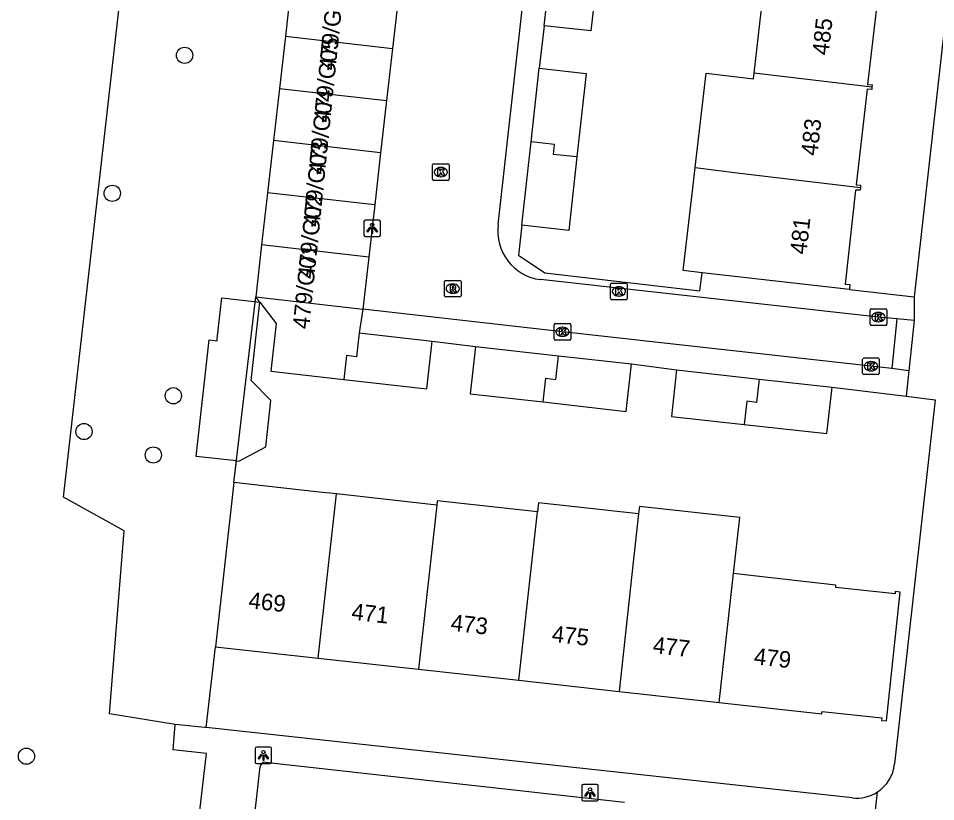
# Model space of a CAD drawing. Extents: x 161928 to 163055, y 386475 to 387428.
# Drawn here: x 162043.6 to 162098.9, y 387056.3 to 387103.5 of the extents above; entities that cross this region are included whole.
import ezdxf

# ---------------------------------------------------------------- set-up
doc = ezdxf.new("R2010")
doc.units = 0
for name, color, linetype in [('IMGEO_Boom', 7, 'Continuous'), ('IMGEO_Groenvoorziening', 7, 'Continuous'), ('IMGEO_Hek', 7, 'Continuous'), ('IMGEO_Kolk', 7, 'Continuous'), ('IMGEO_Lichtpunt', 7, 'Continuous'), ('IMGEO_Pand', 7, 'Continuous'), ('IMGEO_Pand_nummerreeks', 7, 'Continuous'), ('IMGEO_Rijbaan_lokaal_open', 7, 'Continuous'), ('IMGEO_Rioolput', 7, 'Continuous'), ('IMGEO_Voetpad_open', 7, 'Continuous')]:
    doc.layers.add(name, color=color, linetype=linetype)

msp = doc.modelspace()

# ---------------------------------------------------------------- linework, layer by layer
at = {"layer": 'IMGEO_Boom'}
for centre in [(162053.658, 387101.262), (162049.298, 387092.95), (162052.981, 387080.756), (162047.592, 387078.601), (162051.773, 387077.187), (162044.124, 387059.042)]:
    msp.add_circle(centre, 0.489, dxfattribs=at)
at = {"layer": 'IMGEO_Groenvoorziening'}
for points in [[(162053.084, 387060.96), (162049.139, 387061.592), (162050.014, 387072.611), (162046.359, 387074.644), (162054.161, 387143.235), (162059.064, 387145.048), (162059.632, 387154.151), (162065.287, 387153.527)], [(162056.626, 387075.526), (162056.78, 387076.828)], [(162054.959, 387060.765), (162055.525, 387065.64)]]:
    msp.add_lwpolyline(points, dxfattribs=at)
at = {"layer": 'IMGEO_Hek'}
msp.add_lwpolyline([(162056.626, 387075.526), (162057.948, 387086.72)], dxfattribs=at)
at = {"layer": 'IMGEO_Kolk'}
for p, q in [((162068.606, 387093.806), (162068.606, 387094.658)), ((162068.681, 387094.732), (162069.533, 387094.732)), ((162069.094, 387094.512), (162069.119, 387094.512)), ((162069.607, 387094.658), (162069.607, 387093.806)), ((162069.117, 387093.952), (162069.092, 387093.952)), ((162069.533, 387093.732), (162068.681, 387093.732)), ((162079.341, 387086.618), (162079.341, 387087.47)), ((162079.416, 387087.544), (162080.268, 387087.544)), ((162079.829, 387087.324), (162079.854, 387087.324)), ((162080.342, 387087.47), (162080.342, 387086.618)), ((162079.852, 387086.764), (162079.827, 387086.764)), ((162080.268, 387086.544), (162079.416, 387086.544)), ((162094.987, 387085.068), (162094.987, 387085.92)), ((162095.062, 387085.994), (162095.914, 387085.994)), ((162095.475, 387085.774), (162095.5, 387085.774)), ((162095.988, 387085.92), (162095.988, 387085.068)), ((162075.943, 387084.181), (162075.943, 387085.033)), ((162076.018, 387085.107), (162076.87, 387085.107)), ((162076.944, 387085.033), (162076.944, 387084.181)), ((162095.498, 387085.214), (162095.473, 387085.214)), ((162076.431, 387084.887), (162076.456, 387084.887)), ((162095.914, 387084.994), (162095.062, 387084.994)), ((162076.87, 387084.107), (162076.018, 387084.107)), ((162076.454, 387084.327), (162076.429, 387084.327)), ((162094.539, 387082.106), (162094.539, 387082.958)), ((162094.614, 387083.032), (162095.466, 387083.032)), ((162095.027, 387082.812), (162095.052, 387082.812)), ((162095.54, 387082.958), (162095.54, 387082.106)), ((162095.05, 387082.252), (162095.025, 387082.252)), ((162095.466, 387082.032), (162094.614, 387082.032))]:
    msp.add_line(p, q, dxfattribs=at)
for points in [[(162068.606, 387093.806), (162068.606, 387094.658)], [(162068.681, 387094.732), (162069.533, 387094.732)], [(162068.927, 387094.432), (162069.05, 387094.432), (162069.05, 387094.281), (162069.18, 387094.432), (162069.344, 387094.432), (162069.198, 387094.281), (162069.351, 387094.032), (162069.199, 387094.032), (162069.114, 387094.196), (162069.05, 387094.129), (162069.05, 387094.032), (162068.927, 387094.032), (162068.927, 387094.432)], [(162069.607, 387094.658), (162069.607, 387093.806)], [(162069.533, 387093.732), (162068.681, 387093.732)], [(162079.341, 387086.618), (162079.341, 387087.47)], [(162079.416, 387087.544), (162080.268, 387087.544)], [(162079.662, 387087.244), (162079.785, 387087.244), (162079.785, 387087.093), (162079.915, 387087.244), (162080.079, 387087.244), (162079.933, 387087.093), (162080.086, 387086.844), (162079.934, 387086.844), (162079.849, 387087.008), (162079.785, 387086.941), (162079.785, 387086.844), (162079.662, 387086.844), (162079.662, 387087.244)], [(162080.342, 387087.47), (162080.342, 387086.618)], [(162080.268, 387086.544), (162079.416, 387086.544)], [(162094.987, 387085.068), (162094.987, 387085.92)], [(162095.062, 387085.994), (162095.914, 387085.994)], [(162095.308, 387085.694), (162095.431, 387085.694), (162095.431, 387085.543), (162095.561, 387085.694), (162095.725, 387085.694), (162095.579, 387085.543), (162095.732, 387085.294), (162095.58, 387085.294), (162095.495, 387085.458), (162095.431, 387085.391), (162095.431, 387085.294), (162095.308, 387085.294), (162095.308, 387085.694)], [(162095.988, 387085.92), (162095.988, 387085.068)], [(162075.943, 387084.181), (162075.943, 387085.033)], [(162076.018, 387085.107), (162076.87, 387085.107)], [(162076.944, 387085.033), (162076.944, 387084.181)], [(162076.264, 387084.807), (162076.387, 387084.807), (162076.387, 387084.656), (162076.517, 387084.807), (162076.681, 387084.807), (162076.535, 387084.656), (162076.688, 387084.407), (162076.536, 387084.407), (162076.451, 387084.571), (162076.387, 387084.504), (162076.387, 387084.407), (162076.264, 387084.407), (162076.264, 387084.807)], [(162095.914, 387084.994), (162095.062, 387084.994)], [(162076.87, 387084.107), (162076.018, 387084.107)], [(162094.539, 387082.106), (162094.539, 387082.958)], [(162094.614, 387083.032), (162095.466, 387083.032)], [(162095.54, 387082.958), (162095.54, 387082.106)], [(162094.86, 387082.732), (162094.983, 387082.732), (162094.983, 387082.581), (162095.113, 387082.732), (162095.277, 387082.732), (162095.131, 387082.581), (162095.284, 387082.332), (162095.132, 387082.332), (162095.047, 387082.496), (162094.983, 387082.429), (162094.983, 387082.332), (162094.86, 387082.332), (162094.86, 387082.732)], [(162095.466, 387082.032), (162094.614, 387082.032)]]:
    msp.add_lwpolyline(points, dxfattribs=at)
for centre, start, end in [((162068.683, 387094.656), 91.552, 178.448), ((162068.683, 387094.656), 91.552, 178.448), ((162069.531, 387094.656), 1.552, 88.448), ((162069.531, 387094.656), 1.552, 88.448), ((162068.683, 387093.808), 181.552, 268.448), ((162068.683, 387093.808), 181.552, 268.448), ((162069.531, 387093.808), 271.552, 358.448), ((162069.531, 387093.808), 271.552, 358.448), ((162079.418, 387087.468), 91.552, 178.448), ((162079.418, 387087.468), 91.552, 178.448), ((162080.266, 387087.468), 1.552, 88.448), ((162080.266, 387087.468), 1.552, 88.448), ((162079.418, 387086.62), 181.552, 268.448), ((162079.418, 387086.62), 181.552, 268.448), ((162080.266, 387086.62), 271.552, 358.448), ((162080.266, 387086.62), 271.552, 358.448), ((162095.064, 387085.918), 91.552, 178.448), ((162095.064, 387085.918), 91.552, 178.448), ((162095.912, 387085.918), 1.552, 88.448), ((162095.912, 387085.918), 1.552, 88.448), ((162076.02, 387085.031), 91.552, 178.448), ((162076.02, 387085.031), 91.552, 178.448), ((162076.868, 387085.031), 1.552, 88.448), ((162076.868, 387085.031), 1.552, 88.448), ((162095.064, 387085.07), 181.552, 268.448), ((162095.064, 387085.07), 181.552, 268.448), ((162095.912, 387085.07), 271.552, 358.448), ((162095.912, 387085.07), 271.552, 358.448), ((162076.02, 387084.183), 181.552, 268.448), ((162076.02, 387084.183), 181.552, 268.448), ((162076.868, 387084.183), 271.552, 358.448), ((162076.868, 387084.183), 271.552, 358.448), ((162094.616, 387082.956), 91.552, 178.448), ((162094.616, 387082.956), 91.552, 178.448), ((162095.464, 387082.956), 1.552, 88.448), ((162095.464, 387082.956), 1.552, 88.448), ((162094.616, 387082.108), 181.552, 268.448), ((162094.616, 387082.108), 181.552, 268.448), ((162095.464, 387082.108), 271.552, 358.448), ((162095.464, 387082.108), 271.552, 358.448)]:
    msp.add_arc(centre, 0.0765, start, end, dxfattribs=at)
for centre, major_axis, ratio, start_param, end_param in [((162069.093, 387094.232), (-0.387, 0.002), 0.722429, 4.712389, 7.853982), ((162069.118, 387094.232), (-0.39, 0.002), 0.717154, 1.570796, 4.712389), ((162079.828, 387087.044), (-0.387, 0.002), 0.722429, 4.712389, 7.853982), ((162079.853, 387087.044), (-0.39, 0.002), 0.717154, 1.570796, 4.712389), ((162095.474, 387085.494), (-0.387, 0.002), 0.722429, 4.712389, 7.853982), ((162095.499, 387085.494), (-0.39, 0.002), 0.717154, 1.570796, 4.712389), ((162076.43, 387084.607), (-0.387, 0.002), 0.722429, 4.712389, 7.853982), ((162076.455, 387084.607), (-0.39, 0.002), 0.717154, 1.570796, 4.712389), ((162095.026, 387082.532), (-0.387, 0.002), 0.722429, 4.712389, 7.853982), ((162095.051, 387082.532), (-0.39, 0.002), 0.717154, 1.570796, 4.712389)]:
    msp.add_ellipse(centre, major_axis=major_axis, ratio=ratio, start_param=start_param, end_param=end_param, dxfattribs=at)
at = {"layer": 'IMGEO_Lichtpunt'}
for p, q in [((162064.468, 387091.246), (162064.468, 387090.439)), ((162064.468, 387091.246), (162064.468, 387090.439)), ((162065.37, 387091.341), (162064.562, 387091.341)), ((162065.37, 387091.341), (162064.562, 387091.341)), ((162065.464, 387090.439), (162065.464, 387091.246)), ((162065.464, 387090.439), (162065.464, 387091.246)), ((162064.562, 387090.345), (162065.37, 387090.345)), ((162064.562, 387090.345), (162065.37, 387090.345)), ((162058.813, 387059.59), (162058.005, 387059.59)), ((162058.813, 387059.59), (162058.005, 387059.59)), ((162057.911, 387059.495), (162057.911, 387058.688)), ((162057.911, 387059.495), (162057.911, 387058.688)), ((162058.907, 387058.688), (162058.907, 387059.495)), ((162058.907, 387058.688), (162058.907, 387059.495)), ((162058.005, 387058.594), (162058.813, 387058.594)), ((162058.005, 387058.594), (162058.813, 387058.594)), ((162077.605, 387057.248), (162077.605, 387056.441)), ((162077.605, 387057.248), (162077.605, 387056.441)), ((162078.507, 387057.343), (162077.699, 387057.343)), ((162078.507, 387057.343), (162077.699, 387057.343)), ((162078.601, 387056.441), (162078.601, 387057.248)), ((162078.601, 387056.441), (162078.601, 387057.248)), ((162077.699, 387056.347), (162078.507, 387056.347)), ((162077.699, 387056.347), (162078.507, 387056.347))]:
    msp.add_line(p, q, dxfattribs=at)
for points in [[(162064.842, 387090.91), (162064.881, 387090.882), (162064.693, 387090.62), (162064.655, 387090.647), (162064.842, 387090.91)], [(162064.944, 387090.862), (162064.991, 387090.862), (162064.991, 387090.54), (162064.944, 387090.54), (162064.944, 387090.862)], [(162065.054, 387090.882), (162065.092, 387090.909), (162065.279, 387090.647), (162065.24, 387090.619), (162065.054, 387090.882)], [(162058.285, 387059.159), (162058.324, 387059.131), (162058.136, 387058.869), (162058.098, 387058.896), (162058.285, 387059.159)], [(162058.387, 387059.111), (162058.434, 387059.111), (162058.434, 387058.789), (162058.387, 387058.789), (162058.387, 387059.111)], [(162058.497, 387059.131), (162058.535, 387059.158), (162058.722, 387058.896), (162058.683, 387058.868), (162058.497, 387059.131)], [(162077.979, 387056.912), (162078.018, 387056.884), (162077.83, 387056.622), (162077.792, 387056.649), (162077.979, 387056.912)], [(162078.081, 387056.864), (162078.128, 387056.864), (162078.128, 387056.542), (162078.081, 387056.542), (162078.081, 387056.864)], [(162078.191, 387056.884), (162078.229, 387056.911), (162078.416, 387056.649), (162078.377, 387056.621), (162078.191, 387056.884)]]:
    msp.add_lwpolyline(points, dxfattribs=at)
for centre in [(162064.967, 387091.044), (162058.41, 387059.293), (162078.104, 387057.046)]:
    msp.add_circle(centre, 0.0994, dxfattribs=at)
for centre, start, end in [((162064.562, 387091.246), 90, 180), ((162064.562, 387091.246), 90, 180), ((162065.37, 387091.246), 0, 90), ((162065.37, 387091.246), 0, 90), ((162064.562, 387090.439), 180, 270), ((162064.562, 387090.439), 180, 270), ((162065.37, 387090.439), 270, 0), ((162065.37, 387090.439), 270, 360), ((162058.005, 387059.495), 90, 180), ((162058.005, 387059.495), 90, 180), ((162058.813, 387059.495), 0, 90), ((162058.813, 387059.495), 0, 90), ((162058.005, 387058.688), 180, 270), ((162058.005, 387058.688), 180, 270), ((162058.813, 387058.688), 270, 0), ((162058.813, 387058.688), 270, 360), ((162077.699, 387057.248), 90, 180), ((162077.699, 387057.248), 90, 180), ((162078.507, 387057.248), 0, 90), ((162078.507, 387057.248), 0, 90), ((162077.699, 387056.441), 180, 270), ((162077.699, 387056.441), 180, 270), ((162078.507, 387056.441), 270, 0), ((162078.507, 387056.441), 270, 360)]:
    msp.add_arc(centre, 0.0946, start, end, dxfattribs=at)
at = {"layer": 'IMGEO_Pand'}
for points in [[(162075.339, 387103.045), (162075.897, 387108.04)], [(162078.646, 387107.128), (162078.155, 387102.731), (162075.339, 387103.045)], [(162087.989, 387100.194), (162088.688, 387106.183)], [(162060.089, 387105.551), (162059.732, 387102.411)], [(162095.733, 387105.345), (162095.715, 387105.165), (162095.484, 387105.185), (162094.822, 387099.501), (162095.106, 387099.49), (162095.099, 387099.348)], [(162066.553, 387104.814), (162066.195, 387101.674)], [(162059.732, 387102.411), (162059.375, 387099.271)], [(162059.732, 387102.411), (162066.195, 387101.674)], [(162066.195, 387101.674), (162065.837, 387098.534)], [(162074.55, 387096.053), (162075.044, 387100.482)], [(162075.044, 387100.482), (162077.87, 387100.167), (162077.309, 387095.141)], [(162084.441, 387094.508), (162085.103, 387100.194), (162087.95, 387099.857), (162087.989, 387100.194)], [(162095.099, 387099.348), (162087.989, 387100.194)], [(162059.375, 387099.271), (162059.018, 387096.13)], [(162059.375, 387099.271), (162065.837, 387098.534)], [(162095.099, 387099.348), (162095.091, 387099.204), (162094.808, 387099.215), (162094.154, 387093.459), (162094.408, 387093.45), (162094.402, 387093.292)], [(162065.837, 387098.534), (162065.479, 387095.394)], [(162059.018, 387096.13), (162058.661, 387092.99)], [(162065.479, 387095.394), (162059.018, 387096.13)], [(162073.989, 387091.03), (162074.55, 387096.053)], [(162077.309, 387095.141), (162075.896, 387095.298), (162075.963, 387095.896), (162074.55, 387096.053)], [(162065.479, 387095.394), (162065.122, 387092.254)], [(162077.309, 387095.141), (162076.815, 387090.715), (162073.989, 387091.03)], [(162084.854, 387088.159), (162083.718, 387088.293), (162084.296, 387093.26), (162084.441, 387094.508)], [(162084.441, 387094.508), (162086.971, 387094.176), (162094.402, 387093.292)], [(162094.402, 387093.292), (162094.397, 387093.134), (162094.114, 387093.144), (162093.483, 387087.47), (162093.763, 387087.46), (162093.752, 387087.149)], [(162058.661, 387092.99), (162058.304, 387089.85)], [(162065.122, 387092.254), (162058.661, 387092.99)], [(162065.122, 387092.254), (162064.764, 387089.114)], [(162058.304, 387089.85), (162057.948, 387086.72)], [(162064.764, 387089.114), (162058.304, 387089.85)], [(162064.764, 387089.114), (162064.406, 387085.974)], [(162093.752, 387087.149), (162084.854, 387088.159)], [(162056.78, 387076.828), (162054.365, 387077.097), (162055.146, 387084.117), (162055.614, 387084.065), (162055.628, 387084.186), (162055.903, 387086.656), (162058.191, 387086.401)], [(162057.948, 387086.72), (162064.406, 387085.974)], [(162058.191, 387086.401), (162057.948, 387086.72)], [(162056.78, 387076.828), (162056.933, 387076.811), (162058.546, 387077.681), (162058.856, 387080.462), (162057.665, 387081.683), (162058.191, 387086.401)], [(162058.191, 387086.401), (162059.176, 387085.107), (162058.853, 387082.236), (162063.258, 387081.739)], [(162064.406, 387085.974), (162064.188, 387084.542)], [(162064.188, 387084.542), (162064.017, 387083.107), (162063.42, 387083.174), (162063.258, 387081.739)], [(162064.188, 387084.542), (162068.583, 387084.046)], [(162063.258, 387081.739), (162068.26, 387081.175), (162068.583, 387084.046)], [(162071.203, 387083.729), (162070.881, 387080.877), (162075.279, 387080.381)], [(162071.203, 387083.729), (162076.198, 387083.165)], [(162075.279, 387080.381), (162075.44, 387081.806), (162076.037, 387081.738), (162076.198, 387083.165)], [(162076.198, 387083.165), (162080.595, 387082.669)], [(162075.279, 387080.381), (162080.273, 387079.817), (162080.595, 387082.669)], [(162083.314, 387082.31), (162083.005, 387079.516), (162087.396, 387079.03)], [(162083.314, 387082.31), (162088.303, 387081.757)], [(162088.303, 387081.757), (162088.148, 387080.359), (162087.551, 387080.425), (162087.396, 387079.03)], [(162088.303, 387081.757), (162092.693, 387081.271)], [(162087.396, 387079.03), (162092.384, 387078.477), (162092.693, 387081.271)], [(162056.626, 387075.526), (162055.525, 387065.64)], [(162062.813, 387074.84), (162061.596, 387074.975), (162056.626, 387075.526)], [(162061.718, 387064.954), (162062.813, 387074.84)], [(162068.857, 387074.171), (162062.813, 387074.84)], [(162068.857, 387074.171), (162067.762, 387064.284)], [(162074.93, 387073.76), (162068.886, 387074.43), (162068.857, 387074.171)], [(162081.034, 387073.639), (162074.99, 387074.308), (162074.93, 387073.76)], [(162086.755, 387070.048), (162087.129, 387073.423), (162081.084, 387074.093), (162081.034, 387073.639)], [(162073.806, 387063.615), (162074.67, 387071.416), (162074.93, 387073.76)], [(162081.034, 387073.639), (162080.712, 387070.732), (162079.85, 387062.945)], [(162085.894, 387062.276), (162086.755, 387070.048)], [(162085.894, 387062.276), (162092.086, 387061.59), (162092.103, 387061.743), (162095.695, 387061.347), (162095.679, 387061.197), (162095.977, 387061.165), (162096.805, 387068.934), (162096.507, 387068.965), (162096.491, 387068.817), (162092.914, 387069.214), (162092.929, 387069.349), (162087.961, 387069.911), (162086.755, 387070.048)], [(162055.525, 387065.64), (162061.718, 387064.954)], [(162061.718, 387064.954), (162067.762, 387064.284)], [(162067.762, 387064.284), (162073.806, 387063.615)], [(162073.806, 387063.615), (162079.85, 387062.945)], [(162079.85, 387062.945), (162085.894, 387062.276)]]:
    msp.add_lwpolyline(points, dxfattribs=at)
at = {"layer": 'IMGEO_Rijbaan_lokaal_open'}
for points in [[(162072.569, 387091.066), (162076.462, 387125.985), (162069.057, 387126.795)], [(162096.605, 387085.381), (162095.488, 387085.494), (162075.107, 387087.756)], [(162096.298, 387082.392), (162095.04, 387082.532), (162076.444, 387084.607), (162064.406, 387085.974)], [(162096.605, 387085.381), (162096.298, 387082.392)], [(162097.645, 387085.295), (162096.605, 387085.381)], [(162097.645, 387085.295), (162097.329, 387082.251)], [(162097.329, 387082.251), (162096.298, 387082.392)]]:
    msp.add_lwpolyline(points, dxfattribs=at)
msp.add_arc((162075.456, 387090.652), 2.916, 171.8302, 263.1294, dxfattribs=at)
at = {"layer": 'IMGEO_Rioolput'}
for p, q in [((162069.323, 387086.782), (162069.323, 387087.634)), ((162069.398, 387087.708), (162070.25, 387087.708)), ((162069.811, 387087.488), (162069.836, 387087.488)), ((162070.324, 387087.634), (162070.324, 387086.782)), ((162070.25, 387086.708), (162069.398, 387086.708)), ((162069.834, 387086.928), (162069.809, 387086.928))]:
    msp.add_line(p, q, dxfattribs=at)
for points in [[(162069.323, 387086.782), (162069.323, 387087.634)], [(162069.398, 387087.708), (162070.25, 387087.708)], [(162069.912, 387087.406), (162069.66, 387087.408), (162069.66, 387087.008)], [(162069.838, 387087.327), (162069.784, 387087.327), (162069.784, 387087.246)], [(162069.784, 387087.246), (162069.836, 387087.246)], [(162070.324, 387087.634), (162070.324, 387086.782)], [(162070.25, 387086.708), (162069.398, 387086.708)], [(162069.66, 387087.008), (162069.784, 387087.008), (162069.784, 387087.17), (162069.795, 387087.17)], [(162069.842, 387087.141), (162069.913, 387087.008), (162070.053, 387087.008), (162069.988, 387087.134)]]:
    msp.add_lwpolyline(points, dxfattribs=at)
for centre, radius, start, end in [((162069.4, 387087.632), 0.0765, 91.552, 178.448), ((162069.4, 387087.632), 0.0765, 91.552, 178.448), ((162069.82, 387087.435), 0.19, 274.7715, 282.9687), ((162069.844, 387087.231), 0.0964, 77.0061, 93.1865), ((162069.858, 387087.288), 0.0378, 276.6634, 79.6772), ((162069.911, 387087.296), 0.109, 350.3612, 89.416), ((162069.909, 387087.296), 0.112, 277.5842, 350.9817), ((162070.248, 387087.632), 0.0765, 1.552, 88.448), ((162070.248, 387087.632), 0.0765, 1.552, 88.448), ((162069.4, 387086.784), 0.0765, 181.552, 268.448), ((162069.4, 387086.784), 0.0765, 181.552, 268.448), ((162069.794, 387087.117), 0.0533, 26.0293, 88.6989), ((162069.893, 387087.081), 0.108, 29.5134, 73.7905), ((162070.248, 387086.784), 0.0765, 271.552, 358.448), ((162070.248, 387086.784), 0.0765, 271.552, 358.448)]:
    msp.add_arc(centre, radius, start, end, dxfattribs=at)
for centre, major_axis, ratio, start_param, end_param in [((162069.81, 387087.208), (-0.387, 0.002), 0.722429, 4.712389, 7.853982), ((162069.835, 387087.208), (-0.39, 0.002), 0.717154, 1.570796, 4.712389)]:
    msp.add_ellipse(centre, major_axis=major_axis, ratio=ratio, start_param=start_param, end_param=end_param, dxfattribs=at)
at = {"layer": 'IMGEO_Voetpad_open'}
for points in [[(162101.718, 387123.058), (162097.649, 387086.723)], [(162075.339, 387103.045), (162075.044, 387100.482)], [(162073.989, 387091.03), (162073.787, 387089.221), (162075.378, 387088.153), (162084.728, 387087.083), (162084.854, 387088.159)], [(162093.752, 387087.149), (162097.649, 387086.723)], [(162097.649, 387086.723), (162097.645, 387085.295)], [(162068.583, 387084.046), (162071.203, 387083.729)], [(162080.595, 387082.669), (162083.314, 387082.31)], [(162097.329, 387082.251), (162097.16, 387080.725)], [(162092.693, 387081.271), (162097.16, 387080.725)], [(162097.16, 387080.725), (162098.906, 387080.512), (162096.828, 387061.825), (162096.466, 387058.574)], [(162053.523, 387046.789), (162054.986, 387059.213), (162052.968, 387059.431), (162053.084, 387060.96)], [(162054.959, 387060.765), (162054.883, 387060.773), (162053.084, 387060.96)], [(162093.91, 387056.533), (162054.959, 387060.765)], [(162058.518, 387058.674), (162080.189, 387056.264)], [(162057.687, 387053.736), (162058.22, 387058.421)], [(162095.417, 387056.883), (162095.178, 387054.709)]]:
    msp.add_lwpolyline(points, dxfattribs=at)
for centre, radius, start, end in [((162058.511, 387058.38), 0.294, 88.6409, 172.0212), ((162094.168, 387058.829), 2.312, 302.701, 353.6728), ((162094.172, 387058.826), 2.307, 263.4876, 302.6627)]:
    msp.add_arc(centre, radius, start, end, dxfattribs=at)

# ---------------------------------------------------------------- texts
at = {"layer": 'IMGEO_Pand_nummerreeks'}
for s, rotation, p in [('479/G06', 84.1737, (162062.754, 387100.334)), ('485', 83.6375, (162092.482, 387101.233)), ('479/G05', 84.1737, (162062.433, 387097.193)), ('479/G04', 84.1737, (162062.113, 387094.052)), ('483', 83.6375, (162091.807, 387095.177)), ('479/G03', 84.1737, (162061.792, 387090.91)), ('479/G02', 84.1737, (162061.471, 387087.763)), ('481', 83.6375, (162091.145, 387089.233)), ('479/G01', 84.1737, (162061.162, 387084.738)), ('469', 353.6789, (162057.479, 387067.959)), ('471', 353.6789, (162063.685, 387067.272)), ('473', 353.6803, (162069.667, 387066.609)), ('475', 353.6803, (162075.761, 387065.934)), ('477', 353.6803, (162081.854, 387065.259)), ('479', 353.6789, (162087.947, 387064.584))]:
    msp.add_text(s, height=1, rotation=rotation, dxfattribs=at).set_placement(p)

doc.saveas('drawing.dxf')
